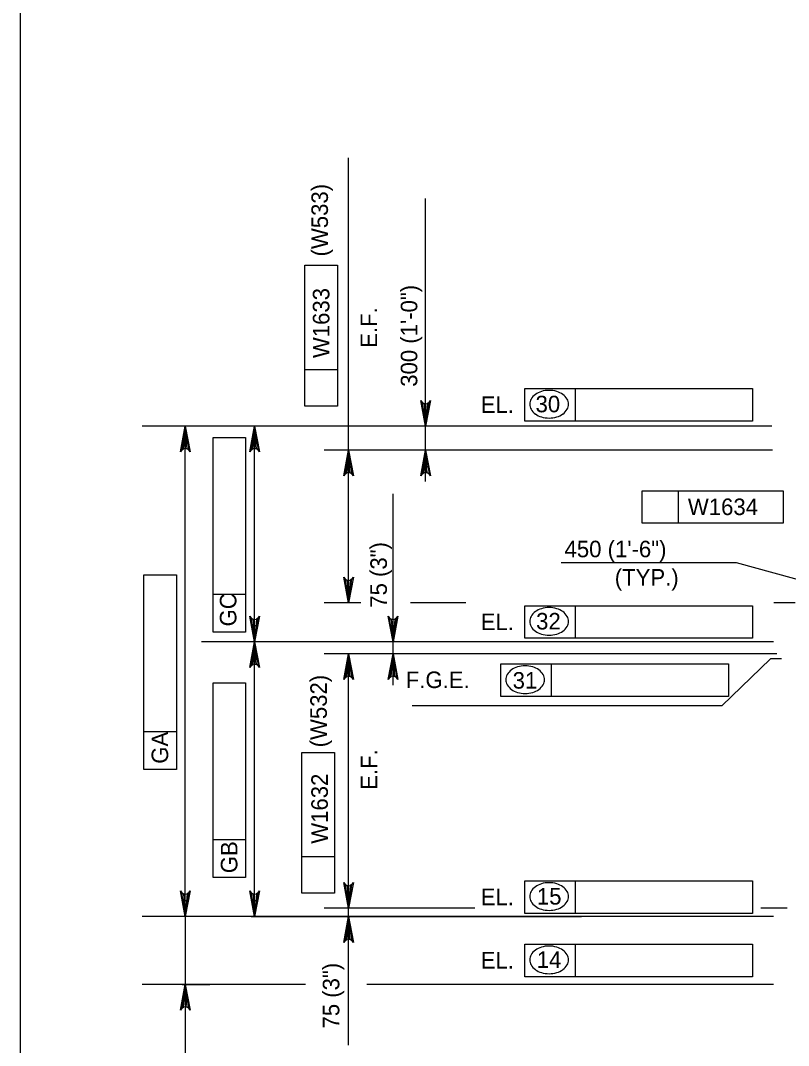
# Model space of a CAD drawing. Extents: x 638340 to 640241, y 295465 to 298435.
# Drawn here: x 639316.5 to 639455.6, y 297949.6 to 298135.5 of the extents above; entities that cross this region are included whole.
import ezdxf

# ---------------------------------------------------------------- set-up
doc = ezdxf.new("R2010")
doc.units = 0
for name, color, linetype in [('2', 7, 'Continuous'), ('3', 7, 'Continuous'), ('4', 7, 'Continuous')]:
    doc.layers.add(name, color=color, linetype=linetype)

msp = doc.modelspace()

# ---------------------------------------------------------------- linework, layer by layer
at = {"layer": '2'}
msp.add_line((639316.46, 297856.46), (639316.46, 298420.46), dxfattribs=at)
at = {"layer": '3'}
msp.add_line((639454.34, 298019.72), (639452.38, 298019.72), dxfattribs=at)
at = {"layer": '4'}
for p, q in [((639375.89, 298032.83), (639375.89, 298110.55)), ((639389.86, 298051.88), (639389.86, 298103.18)), ((639368, 298065.56), (639368, 298091.1)), ((639368, 298091.1), (639373.91, 298091.1)), ((639373.91, 298091.1), (639373.91, 298065.56)), ((639373.91, 298072.15), (639368, 298072.15)), ((639407.87, 298068.74), (639449.08, 298068.74)), ((639407.87, 298062.84), (639407.87, 298068.74)), ((639417.04, 298062.84), (639417.04, 298068.74)), ((639449.08, 298068.74), (639449.08, 298062.84)), ((639373.91, 298065.56), (639368, 298065.56)), ((639452.6, 298061.93), (639338.49, 298061.93)), ((639353.86, 298061.93), (639341.9, 298061.93)), ((639418.3, 298061.93), (639354.44, 298061.93)), ((639449.08, 298062.84), (639407.87, 298062.84)), ((639346.32, 297975.92), (639346.32, 298058.97)), ((639351.34, 298024.55), (639351.34, 298059.85)), ((639351.34, 298059.85), (639357.25, 298059.85)), ((639357.25, 298059.85), (639357.25, 298024.55)), ((639358.87, 298025.75), (639358.87, 298058.97)), ((639452.72, 298057.56), (639371.46, 298057.56)), ((639383.97, 298014.97), (639383.97, 298049.64)), ((639429.09, 298050.21), (639454.63, 298050.21)), ((639429.09, 298044.3), (639429.09, 298050.21)), ((639435.68, 298044.3), (639435.68, 298050.21)), ((639454.63, 298050.21), (639454.63, 298044.3)), ((639454.63, 298044.3), (639429.09, 298044.3)), ((639446.23, 298037.14), (639414.42, 298037.14)), ((639492.01, 298024.51), (639446.23, 298037.14)), ((639338.79, 297999.64), (639338.79, 298034.94)), ((639338.79, 298034.94), (639344.7, 298034.94)), ((639344.7, 298034.94), (639344.7, 297999.64)), ((639357.25, 298031.4), (639351.34, 298031.4)), ((639378.11, 298029.88), (639371.46, 298029.88)), ((639397.17, 298029.88), (639387.15, 298029.88)), ((639407.87, 298029.36), (639449.08, 298029.36)), ((639407.87, 298023.45), (639407.87, 298029.36)), ((639417.04, 298023.45), (639417.04, 298029.36)), ((639449.08, 298029.36), (639449.08, 298023.45)), ((639456.85, 298029.88), (639452.99, 298029.88)), ((639357.25, 298024.55), (639351.34, 298024.55)), ((639449.08, 298023.45), (639407.87, 298023.45)), ((639452.89, 298022.8), (639349.26, 298022.8)), ((639424.71, 298022.8), (639354.44, 298022.8)), ((639418.3, 298022.8), (639354.44, 298022.8)), ((639358.87, 297975.92), (639358.87, 298019.85)), ((639453.49, 298020.65), (639371.46, 298020.65)), ((639452.38, 298019.72), (639443.55, 298011.21)), ((639375.89, 297972.97), (639375.89, 298017.7)), ((639403.52, 298018.79), (639444.73, 298018.79)), ((639403.52, 298012.88), (639403.52, 298018.79)), ((639412.69, 298012.88), (639412.69, 298018.79)), ((639444.73, 298018.79), (639444.73, 298012.88)), ((639351.34, 297980.07), (639351.34, 298015.37)), ((639351.34, 298015.37), (639357.25, 298015.37)), ((639357.25, 298015.37), (639357.25, 297980.07)), ((639444.73, 298012.88), (639403.52, 298012.88)), ((639443.55, 298011.21), (639387.41, 298011.21)), ((639344.7, 298006.48), (639338.79, 298006.48)), ((639367.45, 297977.21), (639367.45, 298002.75)), ((639367.45, 298002.75), (639373.36, 298002.75)), ((639373.36, 298002.75), (639373.36, 297977.21)), ((639344.7, 297999.64), (639338.79, 297999.64)), ((639357.25, 297986.92), (639351.34, 297986.92)), ((639373.36, 297983.81), (639367.45, 297983.81)), ((639357.25, 297980.07), (639351.34, 297980.07)), ((639407.87, 297979.47), (639449.08, 297979.47)), ((639407.87, 297973.56), (639407.87, 297979.47)), ((639417.04, 297973.56), (639417.04, 297979.47)), ((639449.08, 297979.47), (639449.08, 297973.56)), ((639373.36, 297977.21), (639367.45, 297977.21)), ((639398.78, 297974.51), (639371.46, 297974.51)), ((639455.37, 297974.51), (639450.59, 297974.51)), ((639452.89, 297972.97), (639338.49, 297972.97)), ((639353.86, 297972.97), (639341.9, 297972.97)), ((639346.32, 297972.97), (639346.32, 297960.67)), ((639424.71, 297972.97), (639354.44, 297972.97)), ((639358.28, 297972.97), (639418.13, 297972.97)), ((639449.08, 297973.56), (639407.87, 297973.56)), ((639375.89, 297949.67), (639375.89, 297970.02)), ((639407.87, 297967.98), (639449.08, 297967.98)), ((639407.87, 297962.07), (639407.87, 297967.98)), ((639417.04, 297962.07), (639417.04, 297967.98)), ((639449.08, 297967.98), (639449.08, 297962.07)), ((639449.08, 297962.07), (639407.87, 297962.07)), ((639368.11, 297960.67), (639338.49, 297960.67)), ((639345.72, 297960.67), (639350.75, 297960.67)), ((639346.32, 297960.67), (639346.32, 297923.26)), ((639452.89, 297960.67), (639379.22, 297960.67))]:
    msp.add_line(p, q, dxfattribs=at)
for points in [[(639389.86, 298061.93), (639388.98, 298066.59), (639389.23, 298066.23), (639389.54, 298066.04), (639389.86, 298065.99), (639390.17, 298066.04), (639390.48, 298066.23), (639390.73, 298066.59), (639389.86, 298061.93), (639390.48, 298066.23), (639390.17, 298066.04), (639389.86, 298061.93), (639389.86, 298065.99), (639389.54, 298066.04), (639389.86, 298061.93), (639389.23, 298066.23)], [(639346.32, 298061.93), (639347.2, 298057.27), (639346.95, 298057.62), (639346.64, 298057.81), (639346.32, 298057.86), (639346.01, 298057.81), (639345.7, 298057.62), (639345.45, 298057.27), (639346.32, 298061.93), (639345.7, 298057.62), (639346.01, 298057.81), (639346.32, 298061.93), (639346.32, 298057.86), (639346.64, 298057.81), (639346.32, 298061.93), (639346.95, 298057.62)], [(639358.87, 298061.93), (639359.75, 298057.27), (639359.5, 298057.62), (639359.19, 298057.81), (639358.87, 298057.86), (639358.56, 298057.81), (639358.25, 298057.62), (639358, 298057.27), (639358.87, 298061.93), (639358.25, 298057.62), (639358.56, 298057.81), (639358.87, 298061.93), (639358.87, 298057.86), (639359.19, 298057.81), (639358.87, 298061.93), (639359.5, 298057.62)], [(639375.89, 298057.56), (639376.77, 298052.9), (639376.52, 298053.26), (639376.21, 298053.44), (639375.89, 298053.5), (639375.58, 298053.44), (639375.27, 298053.26), (639375.02, 298052.9), (639375.89, 298057.56), (639375.27, 298053.26), (639375.58, 298053.44), (639375.89, 298057.56), (639375.89, 298053.5), (639376.21, 298053.44), (639375.89, 298057.56), (639376.52, 298053.26)], [(639389.86, 298057.56), (639390.73, 298052.9), (639390.48, 298053.26), (639390.17, 298053.44), (639389.86, 298053.5), (639389.54, 298053.44), (639389.23, 298053.26), (639388.98, 298052.9), (639389.86, 298057.56), (639389.23, 298053.26), (639389.54, 298053.44), (639389.86, 298057.56), (639389.86, 298053.5), (639390.17, 298053.44), (639389.86, 298057.56), (639390.48, 298053.26)], [(639375.89, 298029.88), (639375.02, 298034.54), (639375.27, 298034.18), (639375.58, 298033.99), (639375.89, 298033.94), (639376.21, 298033.99), (639376.52, 298034.18), (639376.77, 298034.54), (639375.89, 298029.88), (639376.52, 298034.18), (639376.21, 298033.99), (639375.89, 298029.88), (639375.89, 298033.94), (639375.58, 298033.99), (639375.89, 298029.88), (639375.27, 298034.18)], [(639358.87, 298022.8), (639358, 298027.46), (639358.25, 298027.1), (639358.56, 298026.92), (639358.87, 298026.86), (639359.19, 298026.92), (639359.5, 298027.1), (639359.75, 298027.46), (639358.87, 298022.8), (639359.5, 298027.1), (639359.19, 298026.92), (639358.87, 298022.8), (639358.87, 298026.86), (639358.56, 298026.92), (639358.87, 298022.8), (639358.25, 298027.1)], [(639383.97, 298022.8), (639383.09, 298027.46), (639383.34, 298027.1), (639383.65, 298026.92), (639383.97, 298026.86), (639384.28, 298026.92), (639384.59, 298027.1), (639384.84, 298027.46), (639383.97, 298022.8), (639384.59, 298027.1), (639384.28, 298026.92), (639383.97, 298022.8), (639383.97, 298026.86), (639383.65, 298026.92), (639383.97, 298022.8), (639383.34, 298027.1)], [(639358.87, 298022.8), (639359.75, 298018.14), (639359.5, 298018.5), (639359.19, 298018.69), (639358.87, 298018.74), (639358.56, 298018.69), (639358.25, 298018.5), (639358, 298018.14), (639358.87, 298022.8), (639358.25, 298018.5), (639358.56, 298018.69), (639358.87, 298022.8), (639358.87, 298018.74), (639359.19, 298018.69), (639358.87, 298022.8), (639359.5, 298018.5)], [(639375.89, 298020.65), (639376.77, 298015.99), (639376.52, 298016.35), (639376.21, 298016.53), (639375.89, 298016.58), (639375.58, 298016.53), (639375.27, 298016.35), (639375.02, 298015.99), (639375.89, 298020.65), (639375.27, 298016.35), (639375.58, 298016.53), (639375.89, 298020.65), (639375.89, 298016.58), (639376.21, 298016.53), (639375.89, 298020.65), (639376.52, 298016.35)], [(639383.97, 298020.65), (639384.84, 298015.99), (639384.59, 298016.35), (639384.28, 298016.53), (639383.97, 298016.58), (639383.65, 298016.53), (639383.34, 298016.35), (639383.09, 298015.99), (639383.97, 298020.65), (639383.34, 298016.35), (639383.65, 298016.53), (639383.97, 298020.65), (639383.97, 298016.58), (639384.28, 298016.53), (639383.97, 298020.65), (639384.59, 298016.35)], [(639375.89, 297974.51), (639375.02, 297979.17), (639375.27, 297978.81), (639375.58, 297978.63), (639375.89, 297978.57), (639376.21, 297978.63), (639376.52, 297978.81), (639376.77, 297979.17), (639375.89, 297974.51), (639376.52, 297978.81), (639376.21, 297978.63), (639375.89, 297974.51), (639375.89, 297978.57), (639375.58, 297978.63), (639375.89, 297974.51), (639375.27, 297978.81)], [(639346.32, 297972.97), (639345.45, 297977.63), (639345.7, 297977.27), (639346.01, 297977.09), (639346.32, 297977.03), (639346.64, 297977.09), (639346.95, 297977.27), (639347.2, 297977.63), (639346.32, 297972.97), (639346.95, 297977.27), (639346.64, 297977.09), (639346.32, 297972.97), (639346.32, 297977.03), (639346.01, 297977.09), (639346.32, 297972.97), (639345.7, 297977.27)], [(639358.87, 297972.97), (639358, 297977.63), (639358.25, 297977.27), (639358.56, 297977.09), (639358.87, 297977.03), (639359.19, 297977.09), (639359.5, 297977.27), (639359.75, 297977.63), (639358.87, 297972.97), (639359.5, 297977.27), (639359.19, 297977.09), (639358.87, 297972.97), (639358.87, 297977.03), (639358.56, 297977.09), (639358.87, 297972.97), (639358.25, 297977.27)], [(639375.89, 297972.97), (639376.77, 297968.31), (639376.52, 297968.67), (639376.21, 297968.85), (639375.89, 297968.91), (639375.58, 297968.85), (639375.27, 297968.67), (639375.02, 297968.31), (639375.89, 297972.97), (639375.27, 297968.67), (639375.58, 297968.85), (639375.89, 297972.97), (639375.89, 297968.91), (639376.21, 297968.85), (639375.89, 297972.97), (639376.52, 297968.67)], [(639346.32, 297960.67), (639347.2, 297956.01), (639346.95, 297956.37), (639346.64, 297956.55), (639346.32, 297956.61), (639346.01, 297956.55), (639345.7, 297956.37), (639345.45, 297956.01), (639346.32, 297960.67), (639345.7, 297956.37), (639346.01, 297956.55), (639346.32, 297960.67), (639346.32, 297956.61), (639346.64, 297956.55), (639346.32, 297960.67), (639346.95, 297956.37)]]:
    msp.add_lwpolyline(points, dxfattribs=at)
for points in [[(639389.36, 298064.88), (639390.35, 298064.88), (639389.86, 298061.93)], [(639345.83, 298058.97), (639346.82, 298058.97), (639346.32, 298061.93)], [(639358.38, 298058.97), (639359.36, 298058.97), (639358.87, 298061.93)], [(639375.4, 298054.61), (639376.39, 298054.61), (639375.89, 298057.56)], [(639389.36, 298054.61), (639390.35, 298054.61), (639389.86, 298057.56)], [(639375.4, 298032.83), (639376.39, 298032.83), (639375.89, 298029.88)], [(639358.38, 298025.75), (639359.36, 298025.75), (639358.87, 298022.8)], [(639383.47, 298025.75), (639384.46, 298025.75), (639383.97, 298022.8)], [(639358.38, 298019.85), (639359.36, 298019.85), (639358.87, 298022.8)], [(639375.4, 298017.7), (639376.39, 298017.7), (639375.89, 298020.65)], [(639383.47, 298017.7), (639384.46, 298017.7), (639383.97, 298020.65)], [(639375.4, 297977.46), (639376.39, 297977.46), (639375.89, 297974.51)], [(639345.83, 297975.92), (639346.82, 297975.92), (639346.32, 297972.97)], [(639358.38, 297975.92), (639359.36, 297975.92), (639358.87, 297972.97)], [(639375.4, 297970.02), (639376.39, 297970.02), (639375.89, 297972.97)], [(639345.83, 297957.72), (639346.82, 297957.72), (639346.32, 297960.67)]]:
    msp.add_lwpolyline(points, close=True, dxfattribs=at)
for centre, radius, start, end in [((639411.37, 298065.43), 2.76, 125.6316, 149.9767), ((639411.9, 298064.7), 3.66, 106.5358, 125.6316), ((639412.24, 298063.54), 4.87, 90, 106.5358), ((639412.24, 298063.54), 4.87, 73.4642, 90), ((639412.59, 298064.7), 3.66, 54.3684, 73.4642), ((639413.12, 298065.43), 2.76, 30.0233, 54.3684), ((639410.57, 298065.9), 1.83, 149.9767, 180), ((639410.57, 298065.9), 1.83, 180, 210.0233), ((639413.92, 298065.9), 1.83, 0, 30.0233), ((639413.92, 298065.9), 1.83, 329.9767, 0), ((639411.37, 298066.36), 2.76, 210.0233, 234.3684), ((639411.9, 298067.1), 3.66, 234.3684, 253.4642), ((639412.59, 298067.1), 3.66, 286.5358, 305.6316), ((639413.12, 298066.36), 2.76, 305.6316, 329.9767), ((639412.24, 298068.26), 4.87, 253.4642, 270), ((639412.24, 298068.26), 4.87, 270, 286.5358), ((639411.9, 298025.31), 3.66, 106.5358, 125.6316), ((639412.24, 298024.15), 4.87, 90, 106.5358), ((639412.24, 298024.15), 4.87, 73.4642, 90), ((639412.59, 298025.31), 3.66, 54.3684, 73.4642), ((639410.57, 298026.51), 1.83, 149.9767, 180), ((639411.37, 298026.04), 2.76, 125.6316, 149.9767), ((639413.12, 298026.04), 2.76, 30.0233, 54.3684), ((639413.92, 298026.51), 1.83, 0, 30.0233), ((639410.57, 298026.51), 1.83, 180, 210.0233), ((639411.37, 298026.98), 2.76, 210.0233, 234.3684), ((639411.9, 298027.71), 3.66, 234.3684, 253.4642), ((639412.59, 298027.71), 3.66, 286.5358, 305.6316), ((639413.12, 298026.98), 2.76, 305.6316, 329.9767), ((639413.92, 298026.51), 1.83, 329.9767, 0), ((639412.24, 298028.87), 4.87, 253.4642, 270), ((639412.24, 298028.87), 4.87, 270, 286.5358), ((639407.03, 298015.48), 2.76, 125.6316, 149.9767), ((639407.55, 298014.74), 3.66, 106.5358, 125.6316), ((639407.9, 298013.58), 4.87, 90, 106.5358), ((639407.9, 298013.58), 4.87, 73.4642, 90), ((639408.24, 298014.74), 3.66, 54.3684, 73.4642), ((639408.77, 298015.48), 2.76, 30.0233, 54.3684), ((639406.22, 298015.94), 1.83, 149.9767, 180), ((639406.22, 298015.94), 1.83, 180, 210.0233), ((639409.58, 298015.94), 1.83, 0, 30.0233), ((639409.58, 298015.94), 1.83, 329.9767, 0), ((639407.03, 298016.41), 2.76, 210.0233, 234.3684), ((639407.55, 298017.14), 3.66, 234.3684, 253.4642), ((639407.9, 298018.3), 4.87, 253.4642, 270), ((639407.9, 298018.3), 4.87, 270, 286.5358), ((639408.24, 298017.14), 3.66, 286.5358, 305.6316), ((639408.77, 298016.41), 2.76, 305.6316, 329.9767), ((639411.37, 297976.16), 2.76, 125.6316, 149.9767), ((639411.9, 297975.42), 3.66, 106.5358, 125.6316), ((639412.24, 297974.26), 4.87, 90, 106.5358), ((639412.24, 297974.26), 4.87, 73.4642, 90), ((639412.59, 297975.42), 3.66, 54.3684, 73.4642), ((639413.12, 297976.16), 2.76, 30.0233, 54.3684), ((639410.57, 297976.62), 1.83, 149.9767, 180), ((639410.57, 297976.62), 1.83, 180, 210.0233), ((639413.92, 297976.62), 1.83, 0, 30.0233), ((639413.92, 297976.62), 1.83, 329.9767, 0), ((639411.37, 297977.09), 2.76, 210.0233, 234.3684), ((639411.9, 297977.82), 3.66, 234.3684, 253.4642), ((639412.59, 297977.82), 3.66, 286.5358, 305.6316), ((639413.12, 297977.09), 2.76, 305.6316, 329.9767), ((639412.24, 297978.98), 4.87, 253.4642, 270), ((639412.24, 297978.98), 4.87, 270, 286.5358), ((639411.9, 297963.93), 3.66, 106.5358, 125.6316), ((639412.24, 297962.77), 4.87, 90, 106.5358), ((639412.24, 297962.77), 4.87, 73.4642, 90), ((639412.59, 297963.93), 3.66, 54.3684, 73.4642), ((639410.57, 297965.13), 1.83, 149.9767, 180), ((639411.37, 297964.67), 2.76, 125.6316, 149.9767), ((639413.12, 297964.67), 2.76, 30.0233, 54.3684), ((639413.92, 297965.13), 1.83, 0, 30.0233), ((639410.57, 297965.13), 1.83, 180, 210.0233), ((639411.37, 297965.6), 2.76, 210.0233, 234.3684), ((639411.9, 297966.33), 3.66, 234.3684, 253.4642), ((639412.59, 297966.33), 3.66, 286.5358, 305.6316), ((639413.12, 297965.6), 2.76, 305.6316, 329.9767), ((639413.92, 297965.13), 1.83, 329.9767, 0), ((639412.24, 297967.49), 4.87, 253.4642, 270), ((639412.24, 297967.49), 4.87, 270, 286.5358)]:
    msp.add_arc(centre, radius, start, end, dxfattribs=at)

# ---------------------------------------------------------------- texts
at = {"layer": '3'}
for s, height, p in [('450 (1\'-6")', 3.0001, (639415.04, 298038.14)), ('(TYP.)', 3, (639424.14, 298033))]:
    msp.add_text(s, height=height, dxfattribs=at).set_placement(p)
at = {"layer": '4'}
for s, height, p in [('(W533)', 3, (639372.17, 298092.69)), ('W1633', 3, (639372.43, 298074.26)), ('300 (1\'-0")', 3.0001, (639388.36, 298069.06)), ('E.F.', 3, (639381.08, 298076.12)), ('75 (3")', 3, (639382.85, 298028.99)), ('GC', 3, (639355.58, 298025.6)), ('(W532)', 3, (639371.97, 298003.67)), ('GA', 3, (639343.21, 298000.7)), ('E.F.', 3, (639381.11, 297995.97)), ('W1632', 3, (639372.15, 297986.19)), ('GB', 3, (639355.76, 297980.85)), ('75 (3")', 3, (639374.23, 297952.69))]:
    msp.add_text(s, height=height, rotation=90, dxfattribs=at).set_placement(p)
for s, p in [('30', (639409.79, 298064.43)), ('EL.', (639399.85, 298064.32)), ('W1634', (639437.39, 298045.79)), ('EL.', (639399.85, 298024.93)), ('32', (639409.89, 298025.05)), ('F.G.E.', (639386.26, 298014.42)), ('31', (639405.64, 298014.32)), ('EL.', (639399.85, 297975.05)), ('15', (639410.03, 297975.16)), ('EL.', (639399.85, 297963.56)), ('14', (639410, 297963.67))]:
    msp.add_text(s, height=3, dxfattribs=at).set_placement(p)

doc.saveas('drawing.dxf')
